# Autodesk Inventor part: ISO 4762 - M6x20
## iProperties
Author: Philippe
Created: 2001-12
Part Number: ISO 4762 - M6x20
Material: Par défaut
Catalog Web Link: file:///C:/Program Files/Autodesk/Inventor 5/Content/Iso/index.htm?doNavigateId=932883F9-F3A7-4770-8571-ED868C9DA26C|3B1F5EAA7F48432BB45DC2D896BFA741|true
Description: Vis cylindrique à six pans creux
Document SubType Name: Standard Catalog Part
Standard: ISO 4762 - M6x20
Designer: Philippe
CLASSIFICATION: 31161501 un/spsc
MANUFACTURER: ISO Système de normes
Control State: 0
Master: False
Checked Out: False
PropertySet Name: Design Tracking Control
Shininess: 20.0
Angle Display Precision: 2
Document Length Units: 11269
Document Angle Units: 11283
Document Time Units: 11279
Document Mass Units: 11290
Document Length Units Precision: 3
Document Angle Units Precision: 2
Compacted: False
PropertySet Name: _Private Model Information
Density: 0.0
Volumn: 0.0
Area: 0.0
PropertySet Name: Model Information
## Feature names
1. Base1
